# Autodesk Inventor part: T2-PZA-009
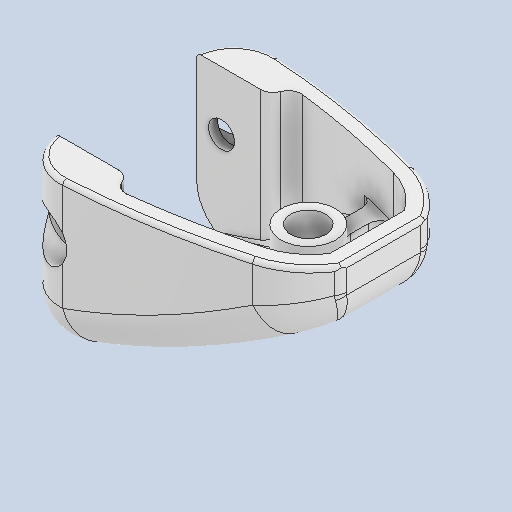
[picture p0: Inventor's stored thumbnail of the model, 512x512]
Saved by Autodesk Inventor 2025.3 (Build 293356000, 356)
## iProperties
Created: 2026-10
Part Number: T2-PZA-009
Material: Genérico
Description: Carcasa distal del dedo
Document SubType Name: Modeling
Designer: Luis MuÃ±oz
Density: 1 g/cm^3
Appearance: Valor por defecto
Project: TESIS 2 - Plataforma mecatrÃ³nica preventiva desacoplada
Sending System: ONSHAPE BY PTC INC, 1.194
Preprocessor: ST-DEVELOPER v20
Material_Fabricacion: PLA
Title: Carcasa distal del dedo
Revision Number: 00
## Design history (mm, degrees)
feature "Distal_Shell"
node "Sólido1"
